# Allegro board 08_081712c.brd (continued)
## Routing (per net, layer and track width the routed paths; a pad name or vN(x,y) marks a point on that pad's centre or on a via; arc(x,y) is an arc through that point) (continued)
TARGET_RESET*: length 458.8
  L8_SIG w0.127: v1(61.4,29.01) 176.4,29.01 188.9,41.5 205.66,41.5 210.51,36.65 218.11,36.65 223.01,31.75 240.5,31.75 243.81,28.44 243.81,25.11 245.43,23.5 v1(245.49,23.5) 248.36,23.5 253.29,28.42 307.82,28.42 325.7,46.3 v1(338.35,46.3)
  BOTTOM w0.127: P33.3 331.34,85.22 331.34,82.88 329.49,81.03 322.71,81.03 319.3,77.62 319.3,70.33 327.13,62.51 327.13,57.53 v1(338.35,46.3) ; U64.2 R547.2 246.19,24.19 v1(245.49,23.5) ; P32.3 16,85.22 16,82.42 14.71,81.13 9.04,81.13 5.46,77.55 5.46,70.48 43.43,32.51 57.9,32.51 v1(61.4,29.01)
TRACE_CLK: length 98.5
  TOP w0.127: SOMA.1 v1(114.15,67.7)
  L8_SIG w0.114: v1(114.15,67.7) 114.15,67.11 115.07,66.18 121.88,66.18 124.69,68.99 131.52,68.99 132.51,68 178.49,68 183.01,72.52 198.98,72.52 P35.12
TRACE_D00: length 97.3
  TOP w0.127: SOMA.3 v1(114.64,68.2)
  L8_SIG w0.114: v1(114.64,68.2) 114.64,67.31 115.39,66.56 121.7,66.56 124.48,69.34 131.66,69.34 132.62,68.38 178.23,68.38 182.75,72.9 198.09,72.9 P35.14
TRACE_D01: length 94.3
  TOP w0.127: SOMA.5 v1(115.15,67.7)
  L8_SIG w0.114: v1(115.15,67.7) 115.15,67.29 115.53,66.9 121.41,66.9 124.23,69.72 131.76,69.72 132.72,68.76 177.98,68.76 182.5,73.28 197.2,73.28 P35.16
TRACE_D02: length 93.2
  TOP w0.127: SOMA.7 v1(115.64,68.2)
  L8_SIG w0.114: v1(115.64,68.2) 115.64,67.36 115.76,67.25 121.09,67.25 123.95,70.1 131.87,70.1 132.83,69.14 177.72,69.14 182.24,73.66 196.31,73.66 P35.18
TRACE_D03: length 89.8
  TOP w0.127: SOMA.9 v1(116.15,67.7)
  L8_SIG w0.114: P35.20 195.42,74.04 181.99,74.04 177.45,69.5 132.95,69.5 131.99,70.46 123.77,70.46 121.01,67.7 v1(116.15,67.7)
TRACE_D04: length 37.4
  TOP w0.127: SOMA.11 v1(116.64,64.27)
  BOTTOM w0.127: v1(116.64,64.27) 116.64,62.62 105.46,51.43 94.87,51.43 92.08,48.64 92.08,46.99 P37.3
TRACE_D05: length 35.6
  TOP w0.127: SOMA.13 v1(117.15,64.78)
  BOTTOM w0.127: P37.5 94.61,46.99 94.61,48.77 96.77,50.93 105.66,50.93 117.15,62.41 v1(117.15,64.78)
TRACE_D06: length 33.7
  TOP w0.127: SOMA.15 v1(117.64,64.27)
  BOTTOM w0.127: v1(117.64,64.27) 117.64,64.15 117.7,64.09 117.7,62.26 105.86,50.42 98.81,50.42 97.16,48.77 97.16,46.99 P37.7
TRACE_D07: length 31.7
  TOP w0.127: SOMA.17 v1(118.15,64.78)
  BOTTOM w0.127: P37.9 99.7,46.99 99.7,48.77 100.84,49.91 106.06,49.91 118.15,62 v1(118.15,64.78)
TWI0_SCL_SOM_A: length 176
  TOP w0.127: SOMA.152 v1(151.9,75.45) ; S12.1A v1(81.53,64.27)
  L3_SIG w0.127: v1(81.53,64.27) 90.28,64.27 92.66,66.66 119.36,66.66 123.6,70.9 136.35,70.9 138.82,73.37 145.65,73.37 146.32,74.04 146.32,75.67 147.41,76.76 151.49,76.76 151.9,76.36 v1(151.9,75.45)
  L8_SIG w0.127: v1(81.53,64.27) 79.44,62.18 61.88,62.18 52.81,53.11 46.84,53.11 34.57,65.38 12.53,65.38 v1(11.87,66.03)
  BOTTOM w0.127: R3.2 151.43,74.17 151.9,74.63 v1(151.9,75.45) 151.9,78.36 152.58,79.05 R588.2 152.65,80.74 U76.1 ; J4.88 v1(11.87,66.03)
TWI0_SCL_SOM_B: length 99.3
  TOP w0.127: v1(327.22,71.72) 327.94,70.99 328.8,70.99 331.04,68.76 335.64,68.76 339.09,65.3 S13.1A ; SOMB.152 v1(278.9,75.45)
  L8_SIG w0.127: v1(327.22,71.72) 327.22,70.55 332.23,65.53 332.23,64.14 330.96,62.86 319.66,62.86 317.99,64.54 299.14,64.54 293.19,70.48 281.13,70.48 280.16,71.45 280.16,72.64 278.9,73.91 v1(278.9,75.45)
  BOTTOM w0.127: P3.88 v1(327.22,71.72) ; U10.1 279.65,80.74 R529.2 279.2,79.05 278.9,78.74 v1(278.9,75.45) 278.87,75.43 278.87,74.47 278.43,74.04 R559.2
TWI0_SDA_SOM_A: length 172.8
  TOP w0.127: SOMA.150 v1(151.39,74.95)
  TOP w0.14: S12.2A v1(78.99,64.27)
  L3_SIG w0.127: v1(151.39,74.95) 151.39,75.83 150.88,76.35 147.57,76.35 146.74,75.51 146.74,73.43 145.95,72.64 139.12,72.64 136.65,70.18 123.9,70.18 119.66,65.94 92.96,65.94 90.58,63.55 79.72,63.55 v1(78.99,64.27)
  L8_SIG w0.127: v1(78.99,64.27) 77.46,62.74 61.85,62.74 54.58,55.47 45.47,55.47 34.91,66.03 v1(13.14,66.03)
  BOTTOM w0.127: R2.2 150.62,73.92 150.62,74.17 v1(151.39,74.95) 151.39,78.35 150.69,79.05 R589.2 150.62,80.74 U76.3 ; J4.84 v1(13.14,66.03)
TWI0_SDA_SOM_B: length 95.7
  TOP w0.127: v1(328.49,70.23) 330.52,68.2 333.5,68.2 336.55,65.15 S13.2A ; SOMB.150 v1(278.39,74.95)
  L8_SIG w0.127: v1(328.49,70.23) 332.61,66.1 332.61,63.8 331.31,62.5 319.52,62.5 317.89,64.14 298.63,64.14 293.22,69.55 280.95,69.55 279.02,71.48 279.02,72.64 278.39,73.27 v1(278.39,74.95)
  BOTTOM w0.127: U10.3 277.62,80.74 R530.2 278.1,79.05 278.39,78.75 v1(278.39,74.95) 278.39,74.66 278.18,74.45 277.6,74.45 277.29,74.14 R558.2 ; P3.84 v1(328.49,70.23)
TWI1_SCL_SOM_A: length 118
  TOP w0.127: S12.4A 73.91,64.95 67.67,71.2 65.11,71.2 v1(64.58,71.72) ; SOMA.158 v1(153.39,74.95)
  L3_SIG w0.127: v1(64.58,71.72) 64.58,70.57 65.35,69.8 68.28,69.8 75.74,62.33 117.37,62.33 124.16,69.11 137.26,69.11 140.03,71.88 149.17,71.88 149.18,71.89 149.43,71.89 151.33,73.79 152.73,73.79 153.39,74.45 v1(153.39,74.95)
  BOTTOM w0.127: R5.2 153.39,73.91 v1(153.39,74.95) ; J5.88 v1(64.58,71.72)
TWI1_SCL_SOM_B: length 119.5
  TOP w0.127: SOMB.158 v1(280.39,74.95)
  TOP w0.14: S13.4A v1(331.47,64.27)
  L3_SIG w0.127: v1(331.47,64.27) 332.78,62.97 376.02,62.97 381.13,68.07 381.13,70.52 v1(379.92,71.72)
  L8_SIG w0.127: v1(280.39,74.95) 280.39,74.44 281.69,73.15 291.91,73.15 299.81,65.25 318.75,65.25 320.28,63.73 326.28,63.73 327.37,64.82 330.92,64.82 v1(331.47,64.27)
  BOTTOM w0.127: P4.88 v1(379.92,71.72) ; R561.2 280.72,73.99 280.39,74.32 v1(280.39,74.95)
TWI1_SDA_SOM_A: length 114
  TOP w0.127: v1(65.85,70.57) 67.4,70.57 71.37,66.6 S12.5A ; SOMA.156 v1(152.9,75.45)
  L3_SIG w0.127: v1(152.9,75.45) 152.9,74.54 152.5,74.14 151.18,74.14 149.28,72.24 139.68,72.24 137.05,69.61 123.95,69.61 117.17,62.83 75.93,62.83 68.46,70.3 66.12,70.3 v1(65.85,70.57)
  BOTTOM w0.127: v1(152.9,75.45) 152.9,73.91 R4.2 ; J5.84 v1(65.85,70.57)
TWI1_SDA_SOM_B: length 124.1
  TOP w0.127: SOMB.156 v1(279.9,75.45)
  TOP w0.14: S13.5A v1(328.93,64.27)
  L3_SIG w0.127: v1(328.93,64.27) 332.6,60.6 374.62,60.6 381.76,67.75 381.76,71.15 v1(381.19,71.72)
  L8_SIG w0.127: v1(279.9,75.45) 279.9,74.05 281.31,72.64 291.7,72.64 299.45,64.9 318.39,64.9 319.91,63.37 326.64,63.37 327.55,64.27 v1(328.93,64.27)
  BOTTOM w0.127: P4.84 v1(381.19,71.72) ; R560.2 279.58,74.09 279.91,74.42 279.91,75.44 v1(279.9,75.45)
TWI2_SCL_SOM_A: length 411.3
  TOP w0.127: SOMA.164 v1(154.9,75.45) ; v1(34.29,115.53) 33.74,115.53 33.2,114.99 U8.23
  TOP w0.14: S12.7A v1(66.29,64.27)
  L3_SIG w0.127: v1(34.29,115.53) 35.36,115.53 57.66,93.23 57.66,70.05 62,65.71 63.75,65.71 65.19,64.27 v1(66.29,64.27) 66.29,65.02 61.49,69.82 61.49,73.48 65.1,77.09 65.1,80.7 73.15,88.75 91.62,88.75 102.74,99.87 114.5,99.87 115.24,99.14 121.45,99.14 122.03,99.72 127.2,99.72 128.37,98.55 128.37,96.82 v1(127.71,96.16) 121.31,89.76 121.31,80.08 123.36,78.03 131.17,78.03 134.89,74.3 144.81,74.3 145.44,74.93 145.44,75.8 148,78.36 153.16,78.36 154.9,76.63 v1(154.9,75.45) ; v1(232.26,103.35) 233.4,104.5 237.13,104.5 243.34,98.29 305.79,98.29 309.07,101.56 309.07,102.44 v1(309.98,103.35)
  L8_SIG w0.127: v1(154.9,75.45) 154.9,75.75 155.19,76.05 185.22,76.05 186.23,75.03 189.3,75.03 189.62,74.71 190.37,74.71 190.68,75.03 193.83,75.03 199.09,80.29 199.09,81.03 201.4,83.34 207.54,83.34 210.06,85.85 210.06,93.27 v1(214.72,97.93)
  BOTTOM w0.127: v1(232.26,103.35) 231.7,102.79 231.7,102.23 231.09,101.63 231.09,100.13 228.12,97.16 215.49,97.16 v1(214.72,97.93) ; R7.2 154.9,74.7 v1(154.9,75.45)
  BOTTOM w0.14: U39.3 v1(127.71,96.16) ; U35.3 v1(309.98,103.35) ; U37.3 v1(232.26,103.35)
TWI2_SCL_SOM_B: length 306.4
  TOP w0.127: v1(262.25,120.61) 261.7,120.61 261.16,120.07 U51.23 ; v1(311.74,103.85) 312.26,103.85 319.53,96.58 319.53,68.59 v1(323.85,64.27) ; SOMB.164 v1(281.9,75.45)
  TOP w0.14: S13.7A v1(323.85,64.27)
  L8_SIG w0.127: v1(281.9,75.45) 281.9,74.84 282.69,74.04 292.28,74.04 300.28,66.04 322.08,66.04 v1(323.85,64.27)
  L8_SIG w0.14: v1(234.01,103.85) 233.46,103.3 233.46,101.77 232.49,100.8 230.14,100.8 229.74,101.2 229.74,101.51 228.84,102.41 228.01,102.41 227.46,101.85 223.52,101.85 222.47,100.8 220.18,100.8 219,101.98 194.56,101.98 193.44,103.1 174.31,103.1 165.58,94.38 136.62,94.38 135.74,93.5 131.39,93.5 v1(129.44,95.45)
  BOTTOM w0.127: R563.2 283.01,74.04 282.75,74.3 282.38,74.3 281.9,74.78 v1(281.9,75.45) 281.9,85.51 266.83,100.57 266.83,117.86 264.08,120.61 v1(262.25,120.61) 258.1,116.46 248.14,116.46 235.54,103.85 v1(234.01,103.85)
  BOTTOM w0.14: U39.2 129.23,95.66 v1(129.44,95.45) ; U35.2 v1(311.74,103.85) ; U37.2 v1(234.01,103.85)
TWI2_SDA_SOM_A: length 409.4
  TOP w0.127: v1(34.32,114.87) 33.71,114.87 33.33,114.49 U8.22 ; SOMA.162 v1(154.39,74.95)
  TOP w0.14: S12.8A v1(63.75,64.27)
  L3_SIG w0.127: v1(311.74,101.85) 310.29,100.41 309.25,100.41 306.63,97.79 243.28,97.79 239.22,101.85 v1(234.01,101.85) ; v1(154.39,74.95) 154.39,76.62 153.03,77.98 148.13,77.98 145.96,75.81 145.96,74.9 145,73.94 134.67,73.94 130.96,77.65 123.24,77.65 120.95,79.93 120.95,89.99 126.54,95.58 126.54,96.65 v1(127.56,97.66) 127.58,97.69 127.58,98.19 126.49,99.29 122.1,99.29 121.6,98.78 115.04,98.78 114.43,99.39 103.3,99.39 91.9,87.98 73.31,87.98 65.94,80.62 65.94,76.61 62.05,72.72 62.05,70.36 67.11,65.3 67.11,63.96 66.47,63.32 64.71,63.32 v1(63.75,64.27) 60.9,64.27 55.86,69.31 55.86,93.33 v1(34.32,114.87)
  L8_SIG w0.127: v1(154.39,74.95) 154.39,76.11 154.81,76.53 185.42,76.53 186.43,75.51 189.32,75.51 189.77,75.07 190.22,75.07 190.66,75.51 193.63,75.51 198.6,80.49 198.6,81.23 201.2,83.82 207.34,83.82 209.58,86.05 209.58,93.9 v1(213.21,97.54)
  BOTTOM w0.127: R6.2 154.39,74.06 v1(154.39,74.95) ; v1(213.21,97.54) 213.98,96.76 228.28,96.76 231.5,99.98 231.5,101.3 232.05,101.85 U37.6 v1(234.01,101.85)
  BOTTOM w0.14: U39.6 v1(127.56,97.66) ; U35.6 v1(311.74,101.85)
TWI2_SDA_SOM_B: length 298.8
  TOP w0.127: U51.22 261.3,119.57 261.68,119.95 v1(262.29,119.95) ; SOMB.162 v1(281.39,74.95) ; v1(321.31,64.27) 318.9,66.69 318.9,96.36 311.93,103.32 310.95,103.32 v1(309.98,102.35)
  TOP w0.14: S13.8A v1(321.31,64.27)
  L8_SIG w0.127: v1(129.44,97.16) 130.07,97.16 132.49,94.74 165.43,94.74 174.37,103.68 194.23,103.68 194.79,103.12 217.17,103.12 217.95,103.9 221.35,103.9 222.94,102.31 227.21,102.31 227.9,103 230.89,103 231.53,102.35 v1(232.26,102.35) ; v1(281.39,74.95) 282.81,73.53 292.07,73.53 299.94,65.66 319.93,65.66 v1(321.31,64.27)
  BOTTOM w0.127: R562.2 281.86,73.99 281.39,74.46 v1(281.39,74.95) 281.39,85 266.19,100.2 266.19,117.86 264.1,119.95 v1(262.29,119.95) 258.42,116.08 248.16,116.08 234.43,102.35 U37.5
  BOTTOM w0.14: U37.5 v1(232.26,102.35) ; U39.5 v1(129.44,97.16) ; U35.5 v1(309.98,102.35)
UART0_CTS_SOM_A*: length 58.3
  TOP w0.127: R436.1 P26.6 ; SOMA.194 v1(162.39,74.95)
  BOTTOM w0.127: v1(162.39,74.95) 162.39,94.45 176.02,108.08 189.36,108.08 P26.6
UART0_CTS_SOM_B*: length 70.5
  TOP w0.127: R437.1 P27.6 ; SOMB.194 v1(289.39,74.95)
  BOTTOM w0.127: v1(289.39,74.95) 289.39,78.7 301.88,91.19 310.9,91.19 319.28,99.57 319.28,107.44 319.91,108.08 333.25,108.08 P27.6
UART0_RTS_SOM_A*: length 46.5
  TOP w0.127: SOMA.192 v1(161.9,75.45)
  BOTTOM w0.127: P26.2 180.97,109.85 179.71,108.58 175.82,108.58 161.9,94.66 v1(161.9,75.45)
UART0_RTS_SOM_B*: length 58.8
  TOP w0.127: SOMB.192 v1(288.9,75.45)
  BOTTOM w0.127: P27.2 323.6,108.58 319.79,108.58 318.78,107.58 318.78,99.78 310.69,91.69 301.67,91.69 288.9,78.91 v1(288.9,75.45)
UART0_RX_SOM_A*: length 53.4
  TOP w0.127: SOMA.190 v1(161.39,74.95)
  BOTTOM w0.127: v1(161.39,74.95) 161.39,94.85 177.8,111.25 184.66,111.25 P26.4
UART0_RX_SOM_B*: length 65.7
  TOP w0.127: SOMB.190 v1(288.39,74.95)
  BOTTOM w0.127: P27.4 328.55,111.25 321.63,111.25 318.24,107.87 318.24,100 310.47,92.22 301.45,92.22 288.39,79.16 v1(288.39,74.95)
UART0_TX_SOM_A*: length 57
  TOP w0.127: SOMA.188 v1(160.9,75.45)
  BOTTOM w0.127: v1(160.9,75.45) 160.9,95.07 177.58,111.76 186.69,111.76 P26.5
UART0_TX_SOM_B*: length 69.3
  TOP w0.127: SOMB.188 v1(287.9,75.45)
  BOTTOM w0.127: v1(287.9,75.45) 287.9,79.32 301.26,92.69 310.27,92.69 317.78,100.19 317.78,108.06 321.47,111.76 330.58,111.76 P27.5
UART1_CTS_SOM_A*: length 52.4
  TOP w0.127: R432.1 P22.6 ; SOMA.204 v1(164.9,75.45)
  BOTTOM w0.127: P22.6 189.36,100.2 177.04,100.2 176.15,101.09 172.97,101.09 164.9,93.01 v1(164.9,75.45)
UART1_CTS_SOM_B*: length 59.6
  TOP w0.127: SOMB.204 v1(291.9,75.45) ; R433.1 P23.6
  BOTTOM w0.127: P23.6 333.25,100.2 323.72,100.2 312.29,88.77 302.87,88.77 291.9,77.8 v1(291.9,75.45)
UART1_RTS_SOM_A*: length 40.7
  TOP w0.127: SOMA.202 v1(164.39,74.95)
  BOTTOM w0.127: v1(164.39,74.95) 164.39,93.22 172.77,101.59 176.28,101.59 177.2,100.67 179.67,100.67 P22.2
UART1_RTS_SOM_B*: length 47.9
  TOP w0.127: SOMB.202 v1(291.39,74.95)
  BOTTOM w0.127: P23.2 312.16,89.27 302.66,89.27 291.39,78.01 v1(291.39,74.95)
UART1_RX_SOM_A*: length 46.8
  TOP w0.127: SOMA.200 v1(163.9,75.45)
  BOTTOM w0.127: v1(163.9,75.45) 163.9,93.43 172.56,102.09 176.39,102.09 177.67,103.38 184.66,103.38 P22.4
UART1_RX_SOM_B*: length 57.2
  TOP w0.127: SOMB.200 v1(290.9,75.45)
  BOTTOM w0.127: v1(290.9,75.45) 290.9,78.22 302.45,89.77 312.01,89.77 320.95,98.71 320.95,102.89 321.44,103.38 328.55,103.38 P23.4
UART1_TX_SOM_A*: length 50.4
  TOP w0.127: SOMA.198 v1(163.39,74.95)
  BOTTOM w0.127: P22.5 186.69,103.89 177.29,103.89 176,102.59 172.35,102.59 163.39,93.63 v1(163.39,74.95)
UART1_TX_SOM_B*: length 60.8
  TOP w0.127: SOMB.198 v1(290.39,74.95)
  BOTTOM w0.127: v1(290.39,74.95) 290.39,78.42 302.24,90.27 311.8,90.27 320.44,98.92 320.44,103.09 321.24,103.89 330.58,103.89 P23.5
UART2_CTS_SOM_A*: length 44.5
  TOP w0.127: SOMA.214 v1(167.39,74.95) ; R434.1 P24.6
  BOTTOM w0.127: v1(167.39,74.95) 167.39,89.04 171.7,93.34 175.89,93.34 177.03,92.21 189.24,92.21 P24.6
UART2_CTS_SOM_B*: length 53.2
  TOP w0.127: SOMB.214 v1(294.39,74.95) ; R435.1 P25.6
  BOTTOM w0.127: v1(294.39,74.95) 294.39,76.59 304.17,86.36 313.45,86.36 319.42,92.33 333.25,92.33 P25.6
UART2_RTS_SOM_A*: length 32.8
  TOP w0.127: SOMA.212 v1(166.9,75.45)
  BOTTOM w0.127: P24.2 179.6,92.74 177.32,92.74 176.21,93.84 171.5,93.84 166.9,89.24 v1(166.9,75.45)
UART2_RTS_SOM_B*: length 41.5
  TOP w0.127: SOMB.212 v1(293.9,75.45)
  BOTTOM w0.127: v1(293.9,75.45) 293.9,76.8 303.96,86.86 313.25,86.86 319.19,92.8 323.56,92.8 P25.2
UART2_RX_SOM_A*: length 38.7
  TOP w0.127: SOMA.210 v1(166.39,74.95)
  BOTTOM w0.127: P24.4 184.62,95.54 177.43,95.54 176.23,94.34 171.29,94.34 166.39,89.45 v1(166.39,74.95)
UART2_RX_SOM_B*: length 48.3
  TOP w0.127: SOMB.210 v1(293.39,74.95)
  BOTTOM w0.127: P25.4 328.55,95.5 321.18,95.5 313.04,87.36 303.75,87.36 293.39,77 v1(293.39,74.95)
UART2_TX_SOM_A*: length 42.4
  TOP w0.127: SOMA.208 v1(165.9,75.45)
  BOTTOM w0.127: v1(165.9,75.45) 165.9,89.66 171.08,94.84 175.87,94.84 177.16,96.14 186.56,96.14 P24.5
UART2_TX_SOM_B*: length 51.9
  TOP w0.127: SOMB.208 v1(292.9,75.45)
  BOTTOM w0.127: P25.5 330.58,96.01 320.98,96.01 312.83,87.86 303.54,87.86 292.9,77.21 v1(292.9,75.45)
UNNAMED_4_ADLT8609_I14_FB: length 7.2
  TOP w0.305: U4.6 401.52,171.49 R454.1 402.07,170.94 405.38,170.94 R456.1 406.9,170.81 C316.1
UNNAMED_4_ADLT8609_I14_INTVCC: length 3
  TOP w0.305: C310.1 395.41,173.99 U4.3
UNNAMED_4_ADLT8609_I14_PG: length 3.2
  TOP w0.305: R452.1 403.99,173.99 U4.8
UNNAMED_4_ADLT8609_I14_RT: length 3.2
  TOP w0.305: R448.1 395.99,173.19 396.3,173.49 U4.4
UNNAMED_4_ADLT8609_I14_TR: length 3.5
  TOP w0.305: U4.7 403.3,173.49 403.61,173.19 C314.1
UNNAMED_4_ADLT8609_I48_FB: length 7.2
  TOP w0.305: U3.6 401.52,128.31 R453.1 402.07,127.76 405.38,127.76 R455.1 406.9,127.63 C315.1
UNNAMED_4_ADLT8609_I48_INTVCC: length 3
  TOP w0.305: U3.3 395.41,130.81 C309.1
UNNAMED_4_ADLT8609_I48_PG: length 3.2
  TOP w0.305: R451.1 403.99,130.81 U3.8
UNNAMED_4_ADLT8609_I48_RT: length 3.2
  TOP w0.305: U3.4 396.3,130.31 395.99,130.01 R447.1
UNNAMED_4_ADLT8609_I48_TR: length 3.5
  TOP w0.305: U3.7 403.3,130.31 403.61,130.01 C313.1
UNNAMED_4_ADLT8609_I60_FB: length 7.2
  TOP w0.305: U50.6 401.52,105.45 R443.1 402.07,104.9 405.38,104.9 R445.1 406.9,104.77 C303.1
UNNAMED_4_ADLT8609_I60_INTVCC: length 3
  TOP w0.305: C296.1 395.41,107.95 U50.3
UNNAMED_4_ADLT8609_I60_PG: length 3.2
  TOP w0.305: U50.8 403.99,107.95 R441.1
UNNAMED_4_ADLT8609_I60_RT: length 3.2
  TOP w0.305: U50.4 396.3,107.45 395.99,107.15 R439.1
UNNAMED_4_ADLT8609_I60_TR: length 3.5
  TOP w0.305: C300.1 403.61,107.15 403.3,107.45 U50.7
UNNAMED_4_CAP_I21_N2: length 4.7
  TOP w1.016: P7.1 332.02,186.69 ; P7.1 330.45,185.13 ; P7.1 328.89,186.69
UNNAMED_11_CAP_I4_N1: length 3.9
  BOTTOM w0.127: U5.1 164.11,26.12 164.11,25.55 163.96,25.4 C1.1 R13.2 R9.2
UNNAMED_11_CAP_I12_N1: length 3.9
  BOTTOM w0.127: R10.2 R14.2 C2.1 162.94,25.4 162.79,25.55 162.79,26.12 U5.3
UNNAMED_11_CMOSNC7SP14_I15_Y: length 2
  BOTTOM w0.127: R17.1 164.4,30.68 U5.6
UNNAMED_11_CMOSNC7SP14_I16_Y: length 2
  BOTTOM w0.127: R18.1 162.5,30.68 U5.4
UNNAMED_11_ICTC7MBL3126_I146_A1: length 70.8
  L8_SIG w0.127: v1(218.79,42.51) 218.38,42.51 216.43,44.46 216.43,49.45 214.83,51.05 192.61,51.05 179.63,38.07 169.9,38.07 v1(164.59,32.77)
  BOTTOM w0.127: R17.2 v1(164.59,32.77)
  BOTTOM w0.14: U7.2 v1(218.79,42.51)
UNNAMED_11_ICTC7MBL3126_I146_A2: length 72.3
  L8_SIG w0.127: v1(218.79,44.46) 218.1,44.46 217.07,45.49 217.07,49.72 215.22,51.56 192.22,51.56 179.37,38.71 168.24,38.71 v1(162.31,32.77)
  BOTTOM w0.127: R18.2 v1(162.31,32.77)
  BOTTOM w0.14: U7.5 v1(218.79,44.46)
UNNAMED_11_RES_I11_N1: length 2.2
  BOTTOM w0.127: R10.1 161.01,23.65 PB2.3
UNNAMED_12_ADLT8618_I115_BST: length 1.5
  TOP w0.203: C351.1 223.26,11.26 U55.1
UNNAMED_12_ADLT8618_I115_INTVCC: length 1.5
  TOP w0.203: C344.1 223.27,12.76 U55.4
UNNAMED_12_ADLT8618_I115_PG: length 1.6
  TOP w0.203: U55.8 R486.2
UNNAMED_12_ADLT8618_I115_RT: length 1.7
  TOP w0.203: U55.5 222.62,13.26 R483.1
UNNAMED_12_ADLT8618_I115_TR: length 2
  TOP w0.203: C347.1 219.46,12.76 U55.7
UNNAMED_12_CAP_I55_N1: length 5.2
  BOTTOM w0.203: E4.1 203.17,18.1 205.49,18.1 206.24,18.86 v2(206.24,19.31)
  BOTTOM w0.508: C327.1 201.96,17.88 E4.1
UNNAMED_12_CAP_I60_N1: length 4.2
  BOTTOM w0.114: 209.04,19.24 208.17,19.24 v2(207.84,18.91)
  BOTTOM w0.203: 209.04,19.24 209.42,19.24 209.9,18.77 E5.1
  BOTTOM w0.508: E5.1 211.69,18.77 C329.1
UNNAMED_12_CN2P_I21_N1: length 12.6
  L8_SIG w0.114: P28.1 198.62,21.03 202.31,21.03 203.82,22.54 204.85,22.54 205.45,21.95 v2(205.45,21.31)
UNNAMED_12_CN2P_I28_N2: length 8.8
  TOP w0.14: v1(203.07,26.5) R473.1 P29.2
  BOTTOM w0.114: v2(205.84,22.51) 205.01,22.51 203.07,24.45 v1(203.07,26.5)
UNNAMED_12_CN24PAB2GND6SHLD_I15: length 1.7
  TOP w0.305: R479.1 206.89,11.85 P9.A5
UNNAMED_12_CN24PAB2GND6SHLD_I_1: length 6.1
  BOTTOM w0.305: P9.B5 208.45,8.12 208.75,7.81 210.64,7.81 210.95,8.12 210.95,8.7 211.19,8.95 R480.1
UNNAMED_12_DIOLED4PV32_I159_CB: length 1.8
  TOP w0.203: R478.2 196.33,19.75 D12.3
UNNAMED_12_DIOLED4PV32_I159_CG: length 1.8
  TOP w0.203: R476.2 196.33,17.97 D12.1
UNNAMED_12_DIOLED4PV32_I159_CR: length 2.2
  TOP w0.203: D12.2 192.84,17.94 191.92,18.86 R477.2
UNNAMED_12_DIOLED_I141_N: length 1.4
  TOP w0.14: R487.1 DS20.C
UNNAMED_12_FERRITE_I19_N2: length 2
  BOTTOM w0.203: E3.2 210.01,20.67 v2(209.05,19.71)
UNNAMED_12_ICATSAMXXXQ21XCFX__1: length 3.4
  TOP w0.14: R472.2 202.43,23.19 v1(202.43,23.18)
  BOTTOM w0.114: v1(202.43,23.18) 203.45,23.18 204.52,22.11 v2(204.65,22.11)
UNNAMED_12_ICATSAMXXXQ21XCFX_I1: length 2.4
  TOP w0.14: R474.1 205.84,24.76 U54.N9
UNNAMED_13_74245V6_I21_1B1: length 2.6
  TOP w0.14: U58.13 214.38,36.13 212.94,37.57 R492.1
UNNAMED_13_74245V6_I21_1B2: length 2.2
  TOP w0.14: R494.1 214.46,37.57 214.88,37.15 U58.12
UNNAMED_13_74245V6_I21_2B1: length 2.2
  TOP w0.14: R493.1 215.81,37.57 215.38,37.14 U58.11
UNNAMED_13_74245V6_I21_2B2: length 2.6
  TOP w0.14: R495.1 217.34,37.57 215.88,36.11 U58.10
UNNAMED_13_74245V6_I68_1A1: length 2.3
  BOTTOM w0.14: R501.2 193.21,34.7 192.27,35.63 U60.4
UNNAMED_13_74245V6_I68_1A2: length 1.8
  BOTTOM w0.14: U60.5 191.77,36.48 R499.2
UNNAMED_13_74245V6_I68_2A1: length 2.3
  BOTTOM w0.14: R500.2 190.33,34.7 191.27,35.64 U60.6
UNNAMED_13_RES_I32_N1: length 2
  TOP w0.14: R489.1 S11.16
UNNAMED_14_DIOLED_I1_N: length 1.4
  TOP w0.508: R420.1 DS7.C
UNNAMED_14_DIOLED_I5_N: length 1.4
  TOP w0.508: R422.1 DS9.C
UNNAMED_14_DIOLED_I7_N: length 1.4
  TOP w0.508: R421.1 DS8.C
UNNAMED_14_DIOLED_I53_N: length 1.4
  TOP w0.508: R425.1 DS12.C
UNNAMED_14_DIOLED_I54_N: length 1.4
  TOP w0.508: R424.1 DS11.C
UNNAMED_14_DIOLED_I57_N: length 1.4
  TOP w0.508: R423.1 DS10.C
USB_5V: length 14.8
  TOP w0.305: P9.B9 206.4,9.38 P9.A4 ; P9.A9 208.89,9.38 P9.B4
  TOP w0.508: TP23.1 218.03,6.29 ; TP23.1 215.8,6.29 ; TP23.1 216.92,5.17 ; TP23.1 216.92,7.4
  L5_PWR w0.508: TP23.1 218.03,6.29 ; TP23.1 215.8,6.29 ; TP23.1 216.92,7.4 ; TP23.1 216.92,5.17 ; P9.B4 208.84,10.02 ; P9.B9 206.45,10.02
  BOTTOM w0.305: P9.B9 206.45,10.55 206.14,10.86 R481.1
USBI_SCL: length 87.9
  TOP w0.127: P30.3 72.01,90.86 70.15,92.71 60.4,92.71 58,90.31 58,56.66 63.45,51.21 65.33,51.21 65.91,51.79 65.91,53.48 S12.7B 66.73,53.43 66.73,51.97 67.54,51.16 72.69,51.16 73.43,51.89 73.43,53.38 S12.4B 74.35,53.43 74.35,51.92 74.96,51.31 80.67,51.31 81.53,52.17 S12.1B
USBI_SCL_B: length 117.8
  TOP w0.127: S13.7B 323.85,51.69 324.43,51.1 330.2,51.1 330.99,51.89 330.99,53.38 S13.4B 331.9,53.43 331.9,51.92 332.51,51.31 338.23,51.31 339.09,52.17 S13.1B ; P31.3 v1(387.35,90.18)
  TOP w0.14: S13.1B v1(339.09,55.66)
  L8_SIG w0.127: v1(339.09,55.66) 340.96,57.53 352.12,57.53 360.27,65.68 371.48,65.68 373.28,63.88 393.22,63.88 396.42,67.08 396.42,81.11 v1(387.35,90.18)
USBI_SDA: length 78
  TOP w0.127: S12.2B 78.59,54.27 78.59,56.24 78.36,56.46 72.42,56.46 71.83,55.88 71.83,54.32 S12.5B 70.92,54.32 70.92,55.8 70.26,56.46 64.64,56.46 64.16,55.98 64.16,54.27 S12.8B 63.35,54.27 63.35,55.47 58.7,60.12 58.7,90.02 60.91,92.23 69.47,92.23 70.74,90.96 P30.5
USBI_SDA_B: length 123.8
  TOP w0.127: S13.2B 336.55,55.83 335.56,56.82 329.87,56.82 329.39,56.34 329.39,54.32 S13.5B 328.47,54.32 328.47,55.8 327.79,56.49 321.89,56.49 321.31,55.91 S13.8B ; P31.5 v1(386.08,90.18)
  TOP w0.14: S13.2B v1(336.55,52.06)
  L8_SIG w0.127: v1(336.55,52.06) 336.55,53.97 340.72,58.15 351.9,58.15 361.95,68.2 370.23,68.2 373.65,64.78 392.85,64.78 395.25,67.18 395.25,81.01 v1(386.08,90.18)
XIN: length 6.8
  TOP w0.14: Y6.1 212.71,15.47 C333.1 v1(212.21,15.94)
  L8_SIG w0.114: v2(208.64,18.11) 210.81,15.94 v1(212.21,15.94)
XIN32: length 4.4
  TOP w0.14: U54.N1 209.05,24.04 209.93,24.92 C335.1 209.93,26.66 Y5.1
XOUT: length 6.8
  TOP w0.14: Y6.3 213.01,20.64 C342.1 v1(212.53,20.19)
  L8_SIG w0.114: v1(212.53,20.19) 210.85,18.51 v2(208.64,18.51)
XOUT32: length 4.4
  TOP w0.14: Y5.2 207.76,26.73 C338.1 208.64,24.07 U54.N2
XSPI_CLK_SOM_A: length 34.6
  TOP w0.127: SOMA.26 v1(120.39,71.52)
  L3_SIG w0.114: v1(99.94,92.14) 99.94,91.07 105.7,85.31 105.7,83.4 115.19,73.91 118,73.91 v1(120.39,71.52)
  BOTTOM w0.114: v1(99.94,92.14) R34.1 99.95,91.31 R38.1
XSPI_CLK_SOM_A*: length 34.5
  TOP w0.127: SOMA.24 v1(119.9,75.2)
  L3_SIG w0.114: v1(101.09,91.02) 106.3,85.82 106.3,83.82 115.55,74.57 118.24,74.57 120.04,72.77 120.27,72.77 120.78,73.28 120.78,73.53 119.9,74.41 v1(119.9,75.2)
  BOTTOM w0.114: v1(101.09,91.02) R36.1
  BOTTOM w0.14: R36.1 R40.1
XSPI_CS1_SOM_A*: length 34.5
  TOP w0.127: SOMA.20 v1(118.9,75.2)
  L3_SIG w0.114: v1(103.39,92.14) 101.8,93.73 101.22,93.73 100.69,93.19 100.69,92.61 107.06,86.23 107.06,84.07 115.97,75.17 118.86,75.17 v1(118.9,75.2)
  BOTTOM w0.14: R37.1 103.38,91.31 R33.2 v1(103.39,92.14)
XSPI_CS2_SOM_A*: length 34.5
  TOP w0.127: SOMA.22 v1(119.39,71.52)
  L3_SIG w0.127: v1(119.39,71.52) 118.49,70.61 113.54,70.61 107.19,76.96 103.89,76.96 103,77.85 97.79,77.85 97.4,78.24 v1(97.4,83.31)
  BOTTOM w0.14: v1(97.4,83.31) R35.2 R39.1
XSPI_DQ0_SOM_A: length 34.6
  TOP w0.127: SOMA.4 114.9,77.35 v1(115.39,77.85)
  L3_SIG w0.114: v1(115.39,77.85) 111.25,81.99 111.25,84.33 110.74,84.84 108.71,84.84 108.33,85.22 108.33,89.15 108.59,89.41 110.49,89.41 110.74,89.15 110.74,88.26 110.51,88.04 109.24,88.04 109.08,87.87 109.08,87.63 109.24,87.46 110.31,87.46 110.47,87.3 110.47,87.06 110.31,86.89 109.24,86.89 109.08,86.73 109.08,86.49 109.24,86.32 v1(112.53,86.32)
  BOTTOM w0.14: R42.2 v1(112.53,86.32)
XSPI_DQ1_SOM_A: length 34.6
  TOP w0.127: SOMA.6 v1(115.39,76.85)
  L3_SIG w0.114: v1(115.39,76.85) 107.7,84.55 107.7,87.23 107.53,87.39 106.72,87.39 106.55,87.56 106.55,87.8 106.72,87.97 107.53,87.97 107.7,88.13 107.7,88.37 107.53,88.54 105.7,88.54 105.54,88.7 105.54,88.94 105.7,89.11 107.53,89.11 107.7,89.28 107.7,89.51 107.53,89.68 106.34,89.68 106.17,89.85 106.17,90.08 106.34,90.25 107.53,90.25 107.7,90.42 107.7,92.58 107.44,92.84 106.68,92.84 106.43,92.58 v1(106.43,91.02)
  BOTTOM w0.14: R46.2 v1(106.43,91.02)
XSPI_DQ2_SOM_A: length 34.5
  TOP w0.127: SOMA.8 v1(115.9,71.52)
  L3_SIG w0.114: 103.79,79.12 104.55,78.36 107.82,78.36 114.05,72.14 115.28,72.14 v1(115.9,71.52)
  L3_SIG w0.127: v1(102.93,79.98) 102.18,79.98 101.99,80.16 101.99,81.09 101.8,81.28 101.54,81.28 101.35,81.09 101.35,80.16 101.17,79.98 100.91,79.98 100.72,80.16 100.72,81.09 100.53,81.28 100.27,81.28 100.08,81.09 100.08,80.16 99.9,79.98 99.57,79.98 99.44,80.11 99.44,81.1 99.26,81.28 98.99,81.28 98.81,81.1 98.81,79.38 99.06,79.12 103.79,79.12
  BOTTOM w0.14: R47.2 v1(102.93,79.98)
XSPI_DQ3_SOM_A: length 34.5
  TOP w0.127: SOMA.10 v1(116.39,72.03)
  L3_SIG w0.114: v1(104.9,79.2) 104.9,79.88 102.74,82.04 100.71,82.04 99.95,82.8 99.95,83.83 100.08,83.96 100.46,83.96 100.58,83.83 100.58,83.19 100.97,82.8 103.21,82.8 106.81,79.2 107.99,79.2 114.43,72.77 117.47,72.77 117.6,72.64 117.6,72.39 117.47,72.26 116.63,72.26 v1(116.39,72.03)
  BOTTOM w0.114: R43.2 v1(104.9,79.2)
XSPI_DQ4_SOM_A: length 34.7
  TOP w0.127: SOMA.12 v1(116.9,71.52)
  L3_SIG w0.114: v1(107.04,79.98) 104.14,82.88 104.14,84.84 103.38,85.6 103.38,85.86 103.62,86.11 104.01,86.11 104.97,85.15 104.97,83.25 114.94,73.28 117.73,73.28 118.49,72.52 118.49,71.88 118.13,71.52 v1(116.9,71.52)
  BOTTOM w0.14: v1(107.04,79.98) R44.2
XSPI_DQ5_SOM_A: length 34.5
  TOP w0.127: SOMA.14 v1(117.39,75.71)
  L3_SIG w0.114: v1(111.38,85.18) 114.01,85.18 114.18,85 114.18,84.77 114.01,84.6 112,84.6 111.83,84.43 111.83,84.19 112,84.03 114.01,84.03 114.18,83.86 114.18,83.62 114.01,83.46 112,83.46 111.83,83.29 111.83,82.35 112.06,82.13 112.29,82.13 112.82,82.65 113.06,82.65 113.22,82.48 113.22,82.25 112.7,81.72 112.7,81.48 112.87,81.32 113.1,81.32 113.63,81.84 113.86,81.84 114.03,81.68 114.03,81.44 113.51,80.91 113.51,80.68 113.67,80.51 113.91,80.51 114.44,81.03 114.67,81.03 114.84,80.87 114.84,80.63 114.31,80.1 114.31,79.87 114.48,79.7 114.72,79.7 115.24,80.23 115.48,80.23 115.65,80.06 115.65,79.82 115.12,79.3 115.12,79.06 115.29,78.89 115.53,78.89 116.05,79.42 116.29,79.42 116.46,79.25 116.46,79.01 115.93,78.49 115.93,78.25 116.1,78.08 116.34,78.08 116.86,78.61 117.1,78.61 117.26,78.44 117.26,78.21 116.74,77.68 116.74,76.36 v1(117.39,75.71)
  BOTTOM w0.14: R48.2 v1(111.38,85.18)
XSPI_DQ6_SOM_A: length 34.6
  TOP w0.127: SOMA.16 v1(117.9,76.21)
  L3_SIG w0.114: v1(117.9,76.21) 117.9,78.95 117.21,79.64 117.21,88.86 117.04,89.03 116.8,89.03 116.64,88.86 116.64,87.63 116.47,87.46 116.23,87.46 116.07,87.63 116.07,88.86 115.9,89.03 115.66,89.03 115.49,88.86 115.49,87.63 115.33,87.46 115.09,87.46 114.92,87.63 114.92,88.86 114.76,89.03 114.52,89.03 114.35,88.86 114.35,87.63 114.18,87.46 113.95,87.46 113.78,87.63 113.78,88.86 113.61,89.03 113.38,89.03 113.21,88.86 113.21,87.63 113.04,87.46 112.8,87.46 112.64,87.63 112.64,88.86 112.47,89.03 112.23,89.03 112.07,88.86 112.07,87.63 111.9,87.46 v1(111.38,87.46)
  BOTTOM w0.14: R45.2 v1(111.38,87.46)
XSPI_DQ7_SOM_A: length 34.5
  TOP w0.127: SOMA.18 v1(118.39,75.71)
  L3_SIG w0.114: v1(118.39,75.71) 118.87,76.18 118.87,89.41 118.03,90.25 112.1,90.25 111.93,90.42 111.93,91.4 111.77,91.57 111.53,91.57 111.36,91.4 111.36,90.42 111.19,90.25 110.96,90.25 110.79,90.42 110.79,91.4 110.62,91.57 110.39,91.57 110.22,91.4 110.22,90.42 110.05,90.25 109.82,90.25 109.65,90.42 109.65,91.4 109.48,91.57 109.24,91.57 109.08,91.4 109.08,90.42 108.91,90.25 v1(108.39,90.25)
  BOTTOM w0.14: R49.2 v1(108.39,90.25)
XSPI_RWDS_SOM_A*: length 34.5
  TOP w0.127: SOMA.2 v1(114.39,71.52)
  L3_SIG w0.114: v1(97.4,87.88) 98.17,87.12 98.17,86.55 97.16,85.54 97.16,84.96 98.17,83.95 98.17,78.87 98.55,78.49 103.38,78.49 104.27,77.6 107.57,77.6 108.59,76.58
  L3_SIG w0.127: v1(114.39,71.52) 113.65,71.52 108.59,76.58
  BOTTOM w0.14: v1(97.4,87.88) R50.2 R51.1 R41.2

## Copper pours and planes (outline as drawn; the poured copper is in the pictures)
0V9 on TOP (solid shape): 134.03,43.86 132.51,43.86 132.21,44.15 132.21,45.3 132.46,45.54 134.03,45.54
0V9 on TOP (solid shape): 137.62,47.64 137.62,46.02 135.95,46.02 135.95,47.64 136.28,47.97 137.28,47.97
0V9 on TOP (solid shape): 141.36,44.54 141.36,43.4 141.07,43.11 139.4,43.11 139.4,44.78 141.11,44.78
0V9 on TOP (solid shape): 147.79,44.43 147.79,42.31 147.79,42.3 144.81,42.3 144.75,42.36 144.75,44.43 144.84,44.52 147.7,44.52
0V9 on BOTTOM: 217.8,73.53 219.07,73.53 219.07,65.66 216.03,65.66 215.14,66.55 215.14,68.45 217.55,70.87 217.55,73.28
0V9 on L6_PWR: 213.87,70.74 219.01,70.74 219.01,66.74 216.66,64.39 216.66,41.15 148.34,41.15 148.34,43.69 130.81,43.69 130.81,48.51 211.2,48.51 211.2,68.07
0V9_B on TOP (solid shape): 261.03,43.86 259.51,43.86 259.21,44.15 259.21,45.3 259.46,45.54 261.03,45.54
0V9_B on TOP (solid shape): 264.62,47.64 264.62,46.02 262.95,46.02 262.95,47.64 263.28,47.97 264.28,47.97
0V9_B on TOP (solid shape): 268.36,44.54 268.36,43.4 268.07,43.11 266.4,43.11 266.4,44.78 268.11,44.78
0V9_B on TOP (solid shape): 274.79,44.43 274.79,42.31 274.79,42.3 271.81,42.3 271.75,42.36 271.75,44.43 271.84,44.52 274.7,44.52
0V9_B on BOTTOM: 220.85,73.53 219.58,73.53 219.58,65.66 222.63,65.66 223.52,66.55 223.52,68.45 221.11,70.87 221.11,73.28
0V9_B on L6_PWR: 219.65,70.74 224.54,70.74 224.92,70.36 224.92,65.02 222.12,62.23 222.12,48.51 275.21,48.51 275.21,43.69 267.21,43.69 267.21,41.15 217.3,41.15 217.3,64.14 219.65,66.49
3V3 on TOP (solid shape): 407.42,128.4 407.29,128.27 405.38,128.27 405.13,128.52 405.13,130.68 405.26,130.81 407.42,130.81
3V3 on TOP (solid shape): 147.83,50.1 147.83,48.22 147.78,48.17 144.79,48.17 144.79,48.18 144.79,50.15 145.01,50.38 147.55,50.38
3V3 on TOP (solid shape): 274.83,50.1 274.83,48.22 274.78,48.17 271.79,48.17 271.79,48.18 271.79,50.15 272.01,50.38 274.55,50.38
3V3 on TOP (solid shape): 222.12,113.41 222.12,112.65 222.25,112.52 223.01,112.52 223.07,112.47 223.07,112.34 223.07,111.8 221.7,111.8 221.49,112.01 221.49,113.41 221.61,113.54 222,113.54
3V3 on TOP (solid shape): 228.47,113.41 228.47,112.65 228.6,112.52 229.36,112.52 229.42,112.46 229.42,112.34 229.42,111.8 228.05,111.8 227.84,112.01 227.84,113.41 227.96,113.54 228.35,113.54
3V3 on TOP (solid shape): 299.85,113.41 299.85,112.65 299.97,112.52 300.74,112.52 300.79,112.47 300.79,112.34 300.79,111.8 299.43,111.8 299.21,112.01 299.21,113.41 299.34,113.54 299.72,113.54
3V3 on TOP (solid shape): 16.63,21.7 16.63,20.3 16.5,20.17 16.12,20.17 15.99,20.3 15.99,21.06 15.87,21.19 15.11,21.19 15.05,21.25 15.05,21.34 15.06,21.39 15.06,21.91 16.41,21.91
3V3 on TOP (solid shape): 384.29,21.7 384.29,20.3 384.17,20.17 383.79,20.17 383.66,20.3 383.66,21.06 383.53,21.19 382.77,21.19 382.71,21.25 382.71,21.34 382.72,21.39 382.72,21.91 384.08,21.91
3V3 on TOP (solid shape): 306.09,113.48 306.16,113.45 306.2,113.41 306.2,112.65 306.32,112.52 307.08,112.52 307.14,112.46 307.14,112.34 307.14,111.8 305.78,111.8 305.56,112.01 305.56,113.23 305.59,113.3 305.67,113.33 305.7,113.33 305.87,113.36 306.02,113.45
3V3 on TOP (solid shape): outline of 85 points within 384.56,136.14 397.13,139.06
3V3 on TOP: 182.59,124.84 182.59,123.37 182.33,123.11 180.65,123.11 180.63,123.12 180.63,123.24 180.83,123.44 180.83,124.18 182.08,124.18 182.08,124.84 182.23,124.99 182.44,124.99
3V3 on TOP: 188.09,88.39 188.09,86.99 188.3,86.78 189.67,86.78 189.67,87.45 189.61,87.5 188.85,87.5 188.72,87.63 188.72,88.39 188.59,88.52 188.21,88.52
3V3 on TOP: 123.95,105.9 123.95,104.5 124.17,104.29 125.53,104.29 125.53,104.95 125.48,105.01 124.71,105.01 124.59,105.14 124.59,105.9 124.46,106.03 124.08,106.03
3V3 on TOP: 112.71,105.87 112.71,104.56 112.99,104.29 114.36,104.29 114.36,104.95 114.3,105.01 113.54,105.01 113.41,105.14 113.41,105.9 113.28,106.03 112.87,106.03
3V3 on BOTTOM: 120.85,105.84 120.85,104.6 120.55,104.31 119.19,104.31 119.19,104.97 119.25,105.03 120.01,105.03 120.13,105.16 120.13,105.92 120.26,106.05 120.64,106.05
3V3 on BOTTOM: 218.95,82.42 218.95,79.63 218.06,79.63 217.93,79.76 217.93,80.77 217.55,81.15 216.03,81.15 215.77,81.41 215.77,82.3 216.03,82.55 218.82,82.55
3V3 on BOTTOM: 188.09,78.85 188.09,80.24 188.31,80.46 189.68,80.46 189.68,79.79 189.62,79.74 188.86,79.74 188.73,79.61 188.73,78.85 188.6,78.72 188.22,78.72
3V3 on L6_PWR: 56.39,150.11 390.78,150.11 390.78,52.7 368.17,52.7 368.17,27.18 401.32,27.18 401.32,7.75 315.85,7.75 312.93,10.67 181.74,10.67 181.61,10.79 103.63,10.79 100.58,7.75 9.91,7.75 9.91,27.05 56.39,27.05
5V on TOP (solid shape): 407.42,171.58 407.29,171.45 405.38,171.45 405.13,171.7 405.13,173.86 405.26,173.99 407.42,173.99
5V on TOP (solid shape): 397.13,180.09 388.21,180.09 388.12,180.13 388.12,180.23 388.2,180.47 388.23,180.72 387.1,181.85 385.97,180.72 385.99,180.47 386.08,180.23 386.07,180.13 385.99,180.09 384.56,180.09 384.56,182.25 397.13,182.25
5V on L6_PWR: 379.73,182.25 404.62,182.25 404.62,41.91 378.97,41.91 378.97,21.72 327.41,21.72 327.41,31.88 368.81,31.88 368.81,52.07 391.41,52.07 391.41,150.75 287.78,150.75 287.78,121.92 280.04,121.92 280.04,150.75 210.06,150.75 210.06,121.92 202.31,121.92 202.31,150.75 55.75,150.75 55.75,33.4 91.57,33.4 91.57,22.1 42.79,22.1 42.79,160.91 379.73,160.91
5V_SOM_A on BOTTOM (solid shape): 109.35,65.41 104.78,65.41 104.78,72.14 109.35,72.14
5V_SOM_A on BOTTOM (solid shape): 96.77,59.18 96.77,57.02 96.52,56.77 94.61,56.77 94.49,56.9 94.49,58.67 95.12,59.31 96.65,59.31
5V_SOM_A on TOP: 104.01,72.01 104.01,65.28 108.71,65.28 108.71,74.68 106.17,77.22 101.73,77.22 100.97,76.45 100.97,75.06
5V_SOM_B on BOTTOM (solid shape): 236.35,65.41 231.77,65.41 231.77,72.14 236.35,72.14
5V_SOM_B on BOTTOM (solid shape): 223.77,59.18 223.77,57.02 223.52,56.77 221.61,56.77 221.49,56.9 221.49,58.67 222.12,59.31 223.65,59.31
5V_SOM_B on TOP: 231.01,72.01 231.01,65.28 235.71,65.28 235.71,74.68 233.17,77.22 228.73,77.22 227.96,76.45 227.96,75.06
10V on TOP (solid shape): 407.42,151.13 407.29,151 405.38,151 405.13,151.26 405.13,153.42 405.26,153.54 407.42,153.54
10V on TOP (solid shape): outline of 85 points within 384.56,158.88 397.13,161.8
10V on L5_PWR: 388.75,162.81 388.75,141.33 187.83,141.33 187.83,162.81
12V on TOP (solid shape): 375.16,182.88 375.16,180.21 374.4,179.45 363.86,179.45 362.97,180.34 362.97,183.26 363.22,183.52 374.52,183.52
12V on TOP (solid shape): 406.02,175.9 406.02,174.75 405.64,174.37 401.07,174.37 401.07,174.62 402.59,174.62 402.84,174.88 402.84,175.64 403.35,176.15 405.77,176.15
12V on TOP (solid shape): outline of 90 points within 401.07,153.92 408.43,156.84
12V on TOP (solid shape): outline of 90 points within 401.07,131.19 408.43,134.11
12V on TOP (solid shape): outline of 90 points within 401.07,108.33 408.43,111.25
12V on BOTTOM (solid shape): 99.06,60.96 99.06,60.2 99.31,59.94 100.84,59.94 100.84,59.69 96.01,59.69 96.01,60.96 96.52,61.47 98.55,61.47
12V on BOTTOM (solid shape): 226.06,60.96 226.06,60.2 226.31,59.94 227.84,59.94 227.84,59.69 223.01,59.69 223.01,60.96 223.52,61.47 225.55,61.47
12V on L5_PWR: 408.56,183.52 408.56,65.15 319.91,65.15 319.91,79.5 389.51,79.5 389.51,163.58 362.7,163.58 362.7,183.52
12V on L5_PWR: 66.17,90.93 66.17,71.5 7.37,71.5 7.37,90.93
12V on L6_PWR: 328.68,79.5 328.68,69.09 239.14,69.09 239.14,49.15 222.76,49.15 222.76,61.98 225.55,64.77 225.55,70.61 224.66,71.5 200.28,71.5 198.37,69.6 176.02,69.6 174.12,71.5 97.54,71.5 97.54,59.69 59.18,59.69 59.18,79.5 175.39,79.5 177.04,77.85 196.85,77.85 198.5,79.5
DGND on TOP (solid shape): 404.37,177.29 402.46,177.29 402.46,180.09 404.37,180.09
DGND on TOP (solid shape): 404.37,156.84 402.46,156.84 402.46,159.64 404.37,159.64
DGND on TOP (solid shape): 404.37,134.11 402.46,134.11 402.46,136.91 404.37,136.91
DGND on TOP (solid shape): 404.37,111.25 402.46,111.25 402.46,114.05 404.37,114.05
DGND on BOTTOM (solid shape): 99.44,62.61 97.54,62.61 97.54,65.41 99.44,65.41
DGND on BOTTOM (solid shape): 112.27,67.69 109.98,67.69 109.98,72.14 112.27,72.14
DGND on BOTTOM (solid shape): 226.44,62.61 224.54,62.61 224.54,65.41 226.44,65.41
DGND on BOTTOM (solid shape): 239.27,67.69 236.98,67.69 236.98,72.14 239.27,72.14
DGND on BOTTOM (solid shape): 235.47,96.75 235.52,96.71 235.56,96.67 235.61,96.6 235.58,96.51 234.25,95.18 234.2,95.1 234.18,95 234.18,94.47 233.82,94.12 232.82,94.12 232.72,94.18 232.75,94.29 235.2,96.75
DGND on BOTTOM (solid shape): 249.37,36.36 249.48,36.38 249.54,36.29 249.54,35.16 247.03,32.65 243.07,32.65 242.47,33.25 242.47,33.33 242.45,33.41 242.5,33.47 242.88,33.09 242.97,33.04 243.07,33.01 245.91,33.01 246.01,33.04 246.1,33.09
DGND on BOTTOM (solid shape): 224.53,88.02 224.56,87.94 224.51,87.87 224.38,87.72 224.33,87.53 224.34,87.46 224.35,87.4 224.34,87.3 224.26,87.26 213.11,87.26 213,87.24 212.92,87.18 212.08,86.35 208.89,86.35 208.78,86.44 208.63,86.48 208.55,86.55 208.57,86.66 210.42,88.51 224.04,88.51
DGND on BOTTOM (solid shape): 83.82,14.53 83.9,14.48 83.91,14.39 83.9,14.35 83.9,14.32 83.89,14.27 83.36,14.27 83.23,14.25 83.11,14.17 82.76,13.82 81.45,13.82 81.35,13.88 81.37,13.99 81.55,14.22 81.67,14.48 81.89,14.48 81.89,14.43 81.96,14.31 82.09,14.26 82.98,14.26 83.13,14.32 83.19,14.46 83.19,14.53
DGND on BOTTOM (solid shape): 346.73,14.5 346.82,14.46 346.83,14.36 346.82,14.33 346.81,14.3 346.81,14.25 346.28,14.25 346.14,14.22 346.03,14.14 345.67,13.79 344.36,13.79 344.27,13.85 344.29,13.96 344.47,14.19 344.59,14.45 344.8,14.45 344.81,14.41 344.87,14.28 345.01,14.23 345.9,14.23 346.04,14.29 346.1,14.44 346.1,14.5
DGND on BOTTOM (solid shape): 121.93,96.01 122,96.1 122.11,96.08 122.74,95.45 122.83,95.39 122.93,95.37 123.29,95.37 123.29,95 123.35,94.86 123.5,94.8 124.33,94.8 124.48,94.86 124.54,95 124.54,95.28 124.53,95.34 124.51,95.39 124.53,95.44 124.54,95.5 124.54,95.56 124.6,95.66 124.71,95.64 127.37,92.98 127.37,88.65 127.31,88.55 127.19,88.58 121.35,94.42 121.26,94.48 121.16,94.5 120.13,94.5 120,94.62 119.98,94.73 120.08,94.8 120.69,94.8 120.78,94.82 120.85,94.87 121.3,94.87 121.4,94.89 121.49,94.95 121.85,95.31 121.91,95.4 121.93,95.5
DGND on BOTTOM (solid shape): outline of 133 points within 198.83,82.46 214.04,86.32
DGND on BOTTOM (solid shape): 139.19,30.96 139.28,30.9 139.41,30.73 139.59,30.61 139.62,30.6 139.62,30.49 139.68,30.35 139.83,30.29 140.86,30.29 140.86,27.33 140.8,27.24 140.7,27.25 140.4,27.39 140.08,27.44 139.33,27.13 139.01,26.38 139.2,25.77 139.71,25.38 139.77,25.28 139.71,25.18 139.45,25.07 139.23,24.89 139.05,24.71 139.02,24.73 138.79,24.81 138.55,24.84 138.07,24.72 137.71,24.38 137.6,24.34 137.52,24.44 137.52,30.29 138.56,30.29 138.7,30.35 138.76,30.49 138.76,30.6 138.79,30.62 138.97,30.73 139.1,30.9
DGND on BOTTOM (solid shape): 266.19,30.96 266.28,30.9 266.41,30.73 266.59,30.61 266.62,30.6 266.62,30.49 266.68,30.35 266.83,30.29 267.86,30.29 267.86,27.33 267.8,27.24 267.7,27.25 267.4,27.39 267.08,27.44 266.33,27.13 266.01,26.38 266.2,25.77 266.71,25.38 266.77,25.28 266.71,25.18 266.45,25.07 266.23,24.89 266.05,24.71 266.02,24.73 265.79,24.81 265.55,24.84 265.07,24.72 264.71,24.38 264.6,24.34 264.52,24.44 264.52,30.29 265.56,30.29 265.7,30.35 265.76,30.49 265.76,30.6 265.79,30.62 265.97,30.73 266.1,30.9
DGND on BOTTOM (solid shape): 136.52,37.34 136.63,37.26 137.07,35.88 137.92,34.71 138.15,34.38 138.23,33.98 138.23,33.31 137.29,33.31 137.14,33.25 137.08,33.11 137.08,33.01 137.05,33 136.73,32.78 136.61,32.42 136.61,22.7 136.58,22.56 136.51,22.45 136.39,22.3 136.31,22.12 136.24,22.06 136.15,22.07 136.08,22.12 136.03,22.2 136.06,22.28 136.34,22.69 136.44,23.18 136.44,32.42 136.32,32.78 136,33 135.97,33.01 135.97,33.11 135.91,33.25 135.76,33.31 134.82,33.31 134.82,33.98 134.9,34.38 135.13,34.71 135.98,35.88 136.42,37.26
DGND on BOTTOM (solid shape): 263.53,37.34 263.63,37.26 264.07,35.88 264.92,34.71 265.15,34.38 265.23,33.98 265.23,33.31 264.29,33.31 264.14,33.25 264.08,33.11 264.08,33.01 264.05,33 263.73,32.78 263.61,32.42 263.61,22.7 263.58,22.56 263.51,22.45 263.39,22.3 263.31,22.12 263.24,22.06 263.15,22.07 263.08,22.12 263.03,22.2 263.06,22.28 263.34,22.69 263.44,23.18 263.44,32.42 263.32,32.78 263,33 262.97,33.01 262.97,33.11 262.91,33.25 262.76,33.31 261.82,33.31 261.82,33.98 261.9,34.38 262.13,34.71 262.98,35.88 263.42,37.26
DGND on BOTTOM (solid shape): outline of 163 points within 202.36,18.4 205.84,22.03
DGND on BOTTOM (solid shape): outline of 112 points within 121.43,75.28 130.67,81.41
DGND on BOTTOM (solid shape): outline of 163 points within 130.07,83.6 138.29,92.05
DGND on BOTTOM (solid shape): outline of 448 points within 131.18,63.79 146.15,77.08
DGND on BOTTOM (solid shape): outline of 593 points within 271.91,59.32 320.93,71.74
DGND on BOTTOM (solid shape): outline of 612 points within 252.91,61.35 268.38,65.2
DGND on BOTTOM (solid shape): outline of 1209 points within 230.89,73.8 261.47,87.44
DGND on BOTTOM (solid shape): outline of 92260 points within 2.54,2.54 412.75,194.31
DGND on L3_SIG (solid shape): outline of 451 points within 58.06,101.24 131.07,102.93
DGND on L8_SIG (solid shape): 166.79,96.79 166.88,96.73 166.86,96.62 165.3,95.06 134.75,95.06 134.66,95.12 134.68,95.23 136.24,96.79
DGND on L8_SIG (solid shape): 242.39,93.43 242.5,93.45 242.56,93.36 242.56,92.68 241.22,91.34 240.54,91.34 240.45,91.4 240.47,91.51
DGND on L8_SIG (solid shape): 228.29,55.1 228.32,54.99 228.22,54.93 228.22,54.93 224.41,54.93 224.31,54.99 224.33,55.1 224.73,55.49 227.9,55.49
DGND on L8_SIG (solid shape): 29.05,112.68 29.16,112.61 29.28,112.58 36.44,112.58 36.88,112.15 36.9,112.04 36.81,111.98 29.51,111.98 27.08,114.41 27.08,114.42 27.06,114.49 27.03,114.56 27.01,114.59 27.08,114.66
DGND on L8_SIG (solid shape): 217.5,104.15 217.6,104.09 217.58,103.98 217.04,103.44 194.92,103.44 194.46,103.91 194.36,103.98 194.23,104 174.7,104 174.65,104.03 174.66,104.09 174.73,104.15
DGND on L8_SIG (solid shape): 228.09,105.34 228.12,105.23 228.02,105.17 225.47,105.17 224.79,105.84 224.69,105.91 224.56,105.94 219.35,105.94 219.26,105.98 219.25,106.07 219.26,106.13 219.27,106.19 219.26,106.24 219.25,106.29 219.27,106.37 219.35,106.41 227.02,106.41
DGND on L8_SIG (solid shape): 240.34,101.26 240.4,101.35 240.51,101.33 241.83,100.02 241.83,94.3 240.22,92.7 240.13,92.67 240.05,92.73 239.96,92.87 239.82,92.96 239.76,93.04 239.79,93.13 241.05,94.39 241.12,94.49 241.14,94.61 241.14,98.2 241.12,98.32 241.05,98.43 240.34,99.13
DGND on L8_SIG (solid shape): 198.11,81.13 198.22,81.15 198.28,81.05 198.28,80.62 193.5,75.83 192.61,75.83 192.51,75.9 192.54,76.01 192.65,76.15 192.68,76.32 192.66,76.47 192.58,76.6 192.56,76.71 192.65,76.77 193.62,76.77 193.75,76.8 193.85,76.86
DGND on L8_SIG (solid shape): 253.17,106.19 253.28,106.13 253.4,106.1 294.82,106.1 295.71,105.22 295.73,105.1 295.63,105.04 294.42,105.04 294.15,105.3 294.05,105.37 293.93,105.4 253.58,105.4 251.28,107.7 251.17,107.77 251.05,107.8 235.05,107.8 234.96,107.84 234.95,107.94 234.97,108 234.98,108.08 234.97,108.17 234.94,108.25 234.94,108.35 235.03,108.39 250.97,108.39
DGND on L8_SIG (solid shape): 241.99,83.16 242.07,83.12 242.09,83.02 242.07,82.96 242.06,82.89 242.16,82.62 242.41,82.48 242.43,82.48 243.09,81.82 243.19,81.75 243.32,81.72 246.91,81.72 247,81.66 246.98,81.55 246.66,81.23 239.68,81.23 239.56,81.29 239.43,81.32 239.38,81.31 239.33,81.31 239.24,81.32 239.2,81.4 239.2,82.16 240.2,83.16
DGND on L8_SIG (solid shape): 229.42,101.37 229.42,101.2 229.44,101.07 229.51,100.97 229.68,100.8 229.7,100.69 229.61,100.63 229.11,100.63 229.02,100.67 229.01,100.75 229.02,100.8 229.02,100.85 228.61,101.26 228.21,100.85 228.21,100.8 228.22,100.75 228.2,100.67 228.12,100.63 223,100.63 222.9,100.69 222.92,100.8 223.65,101.53 227.46,101.53 227.58,101.55 227.69,101.62 228.14,102.08 228.71,102.08
DGND on L8_SIG (solid shape): 256.05,121.07 256.13,121.03 256.27,120.92 256.45,120.88 256.54,120.89 256.63,120.92 256.73,120.92 256.78,120.83 256.78,117.12 251.46,111.81 251.39,111.7 251.37,111.58 251.37,109.47 251.39,109.35 251.46,109.25 253.8,106.91 253.82,106.8 253.73,106.74 253.53,106.74 251.33,108.94 251.23,109.01 251.1,109.03 239.11,109.03 239.02,109.09 239.04,109.2 250.8,120.97 255.4,120.97 255.52,120.9 255.65,120.88 255.83,120.92 255.97,121.03
DGND on L8_SIG (solid shape): 216.08,30.88 216.15,30.97 216.26,30.95 216.39,30.82 216.44,30.78 216.48,30.7 216.44,30.62 216.39,30.58 216.19,30.38 216.12,30.28 216.1,30.16 216.1,25.72 215.77,25.39 209.23,25.39 209.11,25.37 209.01,25.3 208.69,24.98 208.63,24.88 208.6,24.76 208.6,24.07 208.63,23.95 208.69,23.85 209.62,22.92 209.62,21.93 209.57,21.87 209.51,21.86 209.48,21.91 209.48,22.5 209.46,22.62 209.39,22.72 206.54,25.57 206.54,27.53 207.65,28.64 214.12,28.64 214.24,28.67 214.34,28.74 215.99,30.39 216.06,30.49 216.08,30.61
DGND on L8_SIG (solid shape): 5.78,68.97 5.84,69.06 5.96,69.03 5.97,69.02 8.63,66.35 8.74,66.28 8.86,66.26 11.38,66.26 11.46,66.22 11.48,66.13 11.47,66.08 11.47,66.03 11.57,65.77 11.81,65.63 11.83,65.63 12.3,65.15 12.41,65.09 12.53,65.06 26.75,65.06 26.84,65 26.82,64.89 26.74,64.76 26.71,64.61 26.83,64.32 27.11,64.2 27.25,64.23 27.37,64.29 27.95,64.29 28.04,64.24 28.03,64.14 27.99,64.04 27.98,63.93 28,63.8 28.07,63.68 28.07,40.2 20.67,32.81 17.82,32.81 17.73,32.85 17.73,32.95 17.75,33.03 17.76,33.12 17.74,33.25 17.67,33.37 17.67,53.38 17.65,53.51 17.58,53.61 5.78,65.41
DGND on L8_SIG (solid shape): 321.12,90.34 321.22,90.31 321.63,89.91 321.63,87.98 320.83,87.18 320.76,87.08 320.74,86.96 320.74,78.74 320.76,78.62 320.83,78.52 322.28,77.07 322.3,76.96 322.21,76.9 313.37,76.9 313.25,76.87 313.15,76.8 311.06,74.72 304.98,74.72 304.06,75.63 304.04,75.74 304.14,75.81 310.24,75.81 310.36,75.83 310.46,75.9 312.34,77.78 312.41,77.88 312.43,78 312.43,80.21 320.25,88.02 320.4,88.02 320.41,88.01 320.52,87.95 320.65,87.93 320.94,88.05 321.06,88.34 321.03,88.48 320.96,88.61 320.93,88.67 320.96,88.74 321.03,88.86 321.06,89 321.03,89.14 320.96,89.27 320.93,89.33 320.96,89.4 321.03,89.52 321.06,89.66 321.03,89.8 320.96,89.93 320.93,89.99 320.96,90.06 321.02,90.15 321.05,90.26
DGND on L8_SIG (solid shape): outline of 129 points within 122.33,101.63 127.33,103
DGND on L8_SIG (solid shape): 235.16,89.26 235.25,89.22 235.26,89.13 235.25,89.08 235.25,89.02 235.26,88.93 235.29,88.84 235.3,88.76 235.25,88.7 235.22,88.68 235.18,88.65 234.65,88.12 234.59,88.02 234.56,87.9 234.56,86.7 231.93,84.07 231.86,83.97 231.84,83.85 231.84,80.26 231.78,80.17 231.66,80.19 230.45,81.4 230.45,82.87 230.52,82.99 230.54,83.13 230.42,83.41 230.13,83.53 229.97,83.5 229.83,83.4 229.76,83.37 229.68,83.4 229.55,83.5 229.38,83.53 229.24,83.51 229.12,83.44 229.05,83.41 228.99,83.44 228.86,83.51 228.72,83.53 228.58,83.51 228.46,83.44 228.39,83.41 228.33,83.44 228.2,83.51 228.06,83.53 227.92,83.51 227.79,83.43 227.72,83.4 227.65,83.43 227.52,83.51 227.38,83.53 227.37,83.53 227.27,83.6 227.29,83.71 232.85,89.26
DGND on L8_SIG (solid shape): outline of 153 points within 130.35,67.34 194.57,72.21
DGND on L8_SIG (solid shape): 133.15,98.72 133.17,98.63 133.1,98.56 132.89,98.41 132.8,98.16 133.21,97.76 133.62,98.16 133.61,98.22 133.64,98.3 133.71,98.34 134.84,98.34 134.94,98.27 134.91,98.16 133.79,97.04 133.67,97.02 133.61,97.12 133.62,97.16 133.21,97.57 132.8,97.16 132.83,97.02 132.9,96.9 132.93,96.83 132.9,96.76 132.88,96.73 132.86,96.7 132.79,96.65 132.7,96.68 129.83,99.55 129.73,99.62 129.6,99.65 122.13,99.65 122.01,99.62 121.9,99.55 121.63,99.28 120.71,99.28 120.61,99.34 120.62,99.44 120.68,99.56 120.7,99.68 120.67,99.83 120.59,99.96 120.57,100.07 120.66,100.13 131.74,100.13
DGND on L8_SIG (solid shape): 237.77,88.23 237.87,88.16 237.84,88.05 234.22,84.43 234.15,84.32 234.12,84.2 234.12,83.35 234.07,83.27 233.97,83.27 233.88,83.3 233.77,83.32 233.37,82.91 233.77,82.5 233.88,82.52 233.97,82.56 234.07,82.55 234.12,82.47 234.12,80.14 234.15,80.02 234.22,79.91 236.17,77.96 236.19,77.85 236.1,77.79 235.37,77.79 233.03,80.13 233.03,80.44 233.08,80.52 233.17,80.53 233.25,80.51 233.32,80.5 233.73,80.91 233.32,81.32 233.25,81.31 233.17,81.29 233.08,81.3 233.03,81.38 233.03,83.74 235.46,86.17 235.53,86.27 235.55,86.39 235.55,87.03 235.59,87.11 235.68,87.13 235.73,87.12 235.78,87.12 236.07,87.24 236.19,87.52 236.18,87.57 236.18,87.62 236.19,87.71 236.27,87.75 236.66,87.75 236.78,87.78 236.88,87.84 237.27,88.23
DGND on L8_SIG (solid shape): 269.06,83.96 269.16,83.89 269.13,83.78 268.63,83.28 268.57,83.18 268.54,83.06 268.54,82.68 268.4,82.54 268.3,82.51 268.23,82.58 268.08,82.8 267.84,82.88 267.55,82.76 267.43,82.47 267.44,82.4 267.46,82.32 267.45,82.24 267.39,82.19 267.31,82.15 267.24,82.1 267.06,81.92 266.56,81.92 266.48,81.97 266.47,82.06 266.5,82.15 266.51,82.23 266.1,82.64 265.69,82.23 265.7,82.14 265.73,82.06 265.73,81.97 265.65,81.92 265.55,81.89 265.47,81.83 263.97,80.33 258.58,80.33 257.68,81.23 257.58,81.29 257.46,81.32 256.64,81.32 256.52,81.29 256.42,81.23 255.39,80.2 254.12,80.2 254.03,80.26 254.05,80.37 254.61,80.93 254.63,80.95 254.71,80.99 254.79,80.96 254.92,80.85 255.09,80.81 255.38,80.93 255.5,81.22 255.5,81.28 255.48,81.34 255.49,81.42 255.55,81.47 255.62,81.5 255.68,81.54 258.09,83.96
